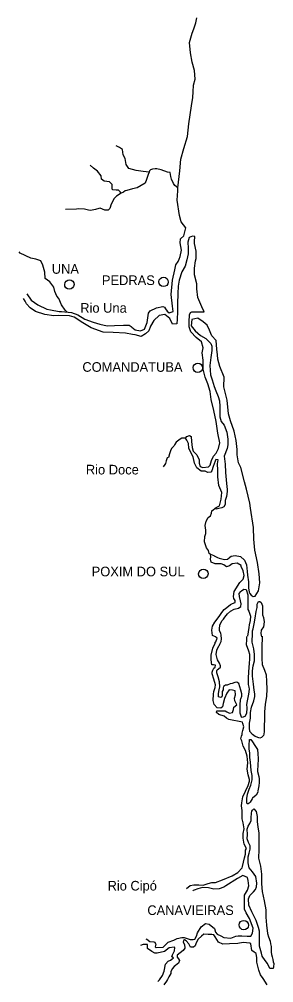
# Model space of a CAD drawing. Extents: x 662444 to 1640468, y 7452018 to 9606170.
# Drawn here: x 1133368 to 1150874, y 8253447 to 8319713 of the extents above; entities that cross this region are included whole.
import ezdxf

# ---------------------------------------------------------------- set-up
doc = ezdxf.new("R2010")
doc.units = 0
for name, color, linetype in [('Level 1', 7, 'Continuous'), ('Level 2', 7, 'Continuous'), ('Level 3', 7, 'Continuous')]:
    doc.layers.add(name, color=color, linetype=linetype)

msp = doc.modelspace()

# ---------------------------------------------------------------- linework, layer by layer
at = {"layer": 'Level 1'}
for points in [[(1145428, 8319196), (1145526, 8319459), (1145579, 8319802)], [(1133894, 8300837), (1134195, 8300395), (1134639, 8300072), (1135257, 8299766), (1135505, 8299737), (1136106, 8299609), (1136268, 8299616), (1136957, 8299553), (1137395, 8299396), (1137883, 8299082), (1138449, 8298878), (1138920, 8298732), (1139414, 8298618), (1139911, 8298649), (1140548, 8298664), (1140937, 8298665), (1141075, 8298583), (1141106, 8298527), (1141350, 8298364), (1141703, 8298277), (1141988, 8298402), (1142162, 8298865), (1142256, 8299507), (1142379, 8299671), (1142805, 8299859), (1143250, 8299958), (1143357, 8299922), (1143429, 8299797), (1143543, 8299627), (1143670, 8299524), (1143953, 8299616), (1143899, 8299984), (1143813, 8300776), (1143905, 8301764), (1144065, 8302471), (1144139, 8302825), (1144308, 8303054), (1144377, 8303208), (1144447, 8303406), (1144534, 8303837), (1144440, 8304329), (1144469, 8304606), (1144691, 8304823), (1144825, 8305364), (1144502, 8305773), (1144395, 8306221), (1144230, 8307271), (1144279, 8307904), (1144285, 8308115), (1144425, 8309279), (1144491, 8310089), (1144695, 8310829), (1144934, 8311656), (1145022, 8312521), (1145218, 8313761), (1145310, 8314337), (1145331, 8314726), (1145365, 8315181), (1145463, 8315601), (1145425, 8316180), (1145268, 8316763), (1145145, 8317400), (1145090, 8318125), (1145269, 8318765), (1145374, 8319051), (1145428, 8319196)], [(1142306, 8309193), (1141897, 8309237), (1141413, 8309306), (1140910, 8309453), (1140723, 8309725), (1140658, 8310139), (1140525, 8310387), (1140497, 8310566), (1140459, 8310745), (1140258, 8310895), (1140045, 8311012)], [(1144285, 8308115), (1144063, 8308277), (1143980, 8308413), (1143848, 8308705), (1143789, 8308907), (1143753, 8309175), (1143559, 8309192), (1143132, 8309359), (1142842, 8309434), (1142713, 8309437), (1142539, 8309409), (1142397, 8309368), (1142320, 8309292), (1142306, 8309193), (1142237, 8309039), (1142130, 8308686), (1142027, 8308444), (1141488, 8308114), (1141162, 8308045), (1140760, 8307945), (1140651, 8307903), (1140530, 8307829), (1140377, 8307755), (1140047, 8307542), (1139903, 8307390), (1139698, 8306995), (1139603, 8306687), (1139492, 8306578), (1139244, 8306585), (1138934, 8306716), (1138684, 8306645), (1138608, 8306625), (1138271, 8306567), (1138121, 8306583), (1137853, 8306657), (1137464, 8306667), (1137313, 8306660), (1136546, 8306637)], [(1140377, 8307755), (1140315, 8307846), (1140199, 8307949), (1140037, 8307965), (1139778, 8307972), (1139750, 8308106), (1139756, 8308339), (1139577, 8308522), (1139212, 8308588), (1139021, 8308715), (1138995, 8308950), (1138755, 8309268), (1138480, 8309475), (1138237, 8309671)], [(1145446, 8304769), (1145295, 8304806), (1145055, 8304702), (1144960, 8304393), (1144992, 8303980), (1144981, 8303580), (1144894, 8303160), (1144774, 8302730), (1144558, 8302346), (1144359, 8301773), (1144293, 8301364), (1144279, 8300852), (1144260, 8300152), (1144244, 8299586), (1144230, 8299085), (1144211, 8298775), (1143918, 8298738), (1143724, 8299133), (1143386, 8299398), (1142985, 8299342), (1142630, 8298985), (1142404, 8298613), (1142287, 8298283), (1142054, 8298089), (1141758, 8297897), (1141340, 8297998), (1141157, 8298036), (1140674, 8298116), (1139822, 8298173), (1139132, 8298203), (1138320, 8298492), (1137747, 8298842), (1137153, 8299214), (1136832, 8299323), (1136098, 8299343), (1135741, 8299308), (1135118, 8299414), (1134487, 8299609), (1134126, 8299864), (1133854, 8300149), (1133772, 8300329), (1133658, 8300499)], [(1147062, 8293779), (1147151, 8293476), (1147161, 8293076), (1147163, 8292364), (1147261, 8292039), (1147470, 8291788), (1147640, 8291305), (1147724, 8290824), (1147713, 8290435), (1147674, 8290181), (1147454, 8289675), (1147535, 8289106), (1147563, 8288549), (1147628, 8287779), (1147671, 8287378), (1147667, 8287244), (1147614, 8286890), (1147541, 8286614), (1147523, 8286347), (1147443, 8286183), (1147300, 8286109), (1147105, 8286059), (1146920, 8286020), (1146913, 8286131), (1147132, 8286247), (1147263, 8286700), (1147298, 8287166), (1147106, 8287638), (1147026, 8288241), (1147028, 8288708), (1146997, 8289143), (1147048, 8289408), (1146897, 8289424), (1146840, 8289314), (1146711, 8288951), (1146606, 8288653), (1146538, 8288566), (1146343, 8288538), (1146151, 8288622), (1145871, 8288629), (1145587, 8288871), (1145433, 8289175), (1145337, 8289612), (1145153, 8289962), (1145030, 8290210), (1145007, 8290544), (1144906, 8290770), (1144812, 8290906), (1144902, 8291014), (1145087, 8291076), (1145204, 8291006), (1145227, 8290683), (1145269, 8290259), (1145338, 8290001), (1145579, 8289750), (1145742, 8289412), (1145735, 8289178), (1145815, 8288953), (1145986, 8288893), (1146397, 8288926), (1146498, 8289035), (1146582, 8289355), (1146731, 8289662), (1146920, 8289879), (1147080, 8290186), (1147156, 8290584), (1147034, 8291244), (1146916, 8292048), (1146754, 8292798), (1146570, 8293570), (1146510, 8294106), (1146341, 8294645), (1146149, 8295095), (1146024, 8295654), (1146008, 8296256), (1145958, 8296780), (1146021, 8297112), (1145914, 8297537), (1145534, 8297815), (1145178, 8298214), (1145058, 8298562), (1145056, 8298896), (1145070, 8299396), (1145150, 8299549), (1145248, 8299602), (1145497, 8299595), (1145950, 8299583), (1146091, 8299601), (1145938, 8299928), (1145643, 8300581), (1145584, 8301183), (1145593, 8301528), (1145427, 8302144), (1145418, 8302601), (1145486, 8303099), (1145534, 8303265), (1145537, 8303765), (1145433, 8304302), (1145427, 8304491), (1145444, 8304702), (1145446, 8304769)], [(1136629, 8299583), (1136529, 8299712), (1136280, 8300072), (1136098, 8300510), (1135962, 8300659), (1135819, 8300985), (1135752, 8301298), (1135460, 8301651), (1135142, 8301893), (1135132, 8302316), (1134995, 8302809), (1134862, 8303091), (1134509, 8303223), (1134165, 8303276), (1133441, 8303630), (1133368, 8303710)], [(1146988, 8278454), (1147167, 8278694), (1147314, 8278912), (1147460, 8279119), (1147636, 8279259), (1147901, 8279452), (1148043, 8279537), (1148218, 8279599), (1148222, 8279743), (1148118, 8279879), (1148111, 8280013), (1148163, 8280345), (1148311, 8280608), (1148390, 8280728), (1148537, 8280969), (1148781, 8281195), (1148842, 8281450), (1148776, 8281785), (1148632, 8282067), (1148634, 8282134), (1148358, 8282297), (1148012, 8282263), (1147836, 8282123), (1147618, 8282062), (1147450, 8282201), (1147257, 8282262), (1146847, 8282251), (1146581, 8282381), (1146532, 8282582), (1146537, 8282738), (1146520, 8282916), (1146755, 8282832), (1146787, 8282798), (1146999, 8282692), (1147128, 8282655), (1147492, 8282567), (1147698, 8282583), (1147819, 8282669), (1147852, 8282712), (1147951, 8282776), (1148212, 8282835), (1148577, 8282770), (1148872, 8282517), (1149002, 8282179), (1149044, 8281733), (1149069, 8281477), (1149132, 8281019), (1149131, 8280618), (1149187, 8280316), (1149228, 8280226), (1149321, 8280101), (1149449, 8280020), (1149600, 8280027), (1149826, 8280410), (1149917, 8280941), (1149881, 8281565), (1149763, 8282358), (1149581, 8283197), (1149495, 8283945), (1149474, 8284758), (1149275, 8286098), (1149241, 8286422), (1149009, 8287385), (1148861, 8287900), (1148619, 8288875), (1148456, 8289213), (1148352, 8289761), (1148363, 8290128), (1148294, 8290742), (1148150, 8291391), (1147900, 8292087), (1147773, 8292569), (1147659, 8293507), (1147447, 8294425), (1147455, 8295092), (1147162, 8295834), (1147036, 8296327), (1147012, 8296639), (1146969, 8297030), (1146920, 8297609), (1146616, 8297940), (1146556, 8298098), (1146455, 8298334), (1146292, 8298683), (1146017, 8298902), (1145657, 8299157), (1145233, 8299058), (1145200, 8298625), (1145460, 8298273), (1145840, 8297962), (1146201, 8297763), (1146537, 8297420), (1146607, 8297229), (1146621, 8296928), (1146542, 8296441), (1146484, 8295897), (1146520, 8295263), (1146640, 8294903), (1146778, 8294454), (1146889, 8294162), (1147062, 8293779)], [(1144812, 8290906), (1144553, 8290902), (1144444, 8290838), (1144168, 8290634), (1144055, 8290448), (1144009, 8290350), (1143843, 8290199), (1143763, 8290034), (1143692, 8289814), (1143632, 8289582), (1143544, 8289540), (1143463, 8289353), (1143426, 8289165), (1143381, 8289088), (1143257, 8288925)], [(1146520, 8282916), (1146436, 8282974), (1146376, 8283165), (1146252, 8283369), (1146112, 8283762), (1146123, 8284129), (1146204, 8284338), (1146200, 8284572), (1146155, 8284884), (1146217, 8285183), (1146364, 8285435), (1146519, 8285564), (1146599, 8285739), (1146626, 8285905), (1146913, 8286131)], [(1149004, 8277252), (1148997, 8277029), (1148988, 8276707), (1149138, 8276280), (1149196, 8276045), (1149218, 8275699), (1149189, 8275422), (1149140, 8274823), (1149117, 8274390), (1149105, 8273967), (1149164, 8273765), (1149182, 8273643), (1149129, 8273299), (1149040, 8272846), (1149011, 8272580), (1149027, 8272357), (1148994, 8271957), (1148880, 8271760), (1148695, 8271699), (1148664, 8271722), (1148563, 8271981), (1148558, 8272170), (1148568, 8272537), (1148590, 8272925), (1148613, 8272980), (1148672, 8273156), (1148676, 8273312), (1148608, 8273559), (1148539, 8273794), (1148481, 8274018), (1148343, 8274111), (1148203, 8274104), (1148017, 8274032), (1147876, 8274002), (1147669, 8273919), (1147550, 8273922), (1147418, 8273815), (1147405, 8273726), (1147401, 8273593), (1147333, 8273472), (1147330, 8273384), (1147324, 8273161), (1147301, 8273117), (1147225, 8273075), (1147085, 8273101), (1147081, 8273346), (1147131, 8273589), (1147169, 8273789), (1147147, 8274134), (1147059, 8274481), (1146959, 8274762), (1146964, 8274907), (1146987, 8274973), (1147064, 8275026), (1147208, 8275144), (1147210, 8275244), (1147140, 8275436), (1147006, 8275651), (1146909, 8276020), (1146950, 8276331), (1147030, 8276484), (1147120, 8276637), (1147142, 8276659), (1147177, 8276725), (1147258, 8276923), (1147273, 8277100), (1147259, 8277345), (1147231, 8277491), (1147149, 8277660), (1147142, 8277794), (1147160, 8278038), (1147298, 8278334), (1147409, 8278453), (1147520, 8278584), (1147689, 8278824), (1147909, 8278995), (1148161, 8279133), (1148455, 8279203), (1148620, 8279320), (1148625, 8279509), (1148577, 8279711), (1148510, 8280013), (1148505, 8280213), (1148617, 8280355), (1148661, 8280398), (1148826, 8280505), (1148987, 8280500), (1149085, 8280130), (1149095, 8279729), (1149086, 8279418), (1149088, 8279107), (1149172, 8279004), (1149270, 8278668), (1149262, 8278368), (1149188, 8278058), (1149161, 8277870), (1149110, 8277593), (1149069, 8277283)], [(1150072, 8277277), (1150067, 8277088), (1150066, 8276688), (1150053, 8276232), (1150050, 8275754), (1150071, 8275341), (1150233, 8274948), (1150353, 8274633), (1150383, 8274165), (1150389, 8273631), (1150386, 8273152), (1150295, 8272577), (1150248, 8272077), (1150236, 8271666), (1150230, 8271455), (1150223, 8271199), (1150210, 8270732), (1150204, 8270543), (1150169, 8270444), (1150025, 8270304), (1149916, 8270262), (1149596, 8270383), (1149406, 8270511), (1149239, 8270716), (1149203, 8270972), (1149212, 8271295), (1149265, 8271638), (1149276, 8272027), (1149351, 8272403), (1149504, 8272833), (1149566, 8273131), (1149571, 8273309), (1149525, 8273577), (1149472, 8273990), (1149412, 8274526), (1149422, 8274893), (1149464, 8275236), (1149549, 8275579), (1149562, 8276034), (1149497, 8276403), (1149392, 8276874), (1149396, 8277018), (1149406, 8277363), (1149414, 8277640), (1149461, 8277784), (1149536, 8278138), (1149600, 8278514), (1149667, 8278979), (1149729, 8279256), (1149736, 8279489), (1149827, 8279675), (1149913, 8279673), (1150008, 8279604), (1150110, 8279367), (1150106, 8279245), (1150091, 8279078), (1150092, 8278745), (1150163, 8278576), (1150219, 8278263), (1150166, 8277931), (1150019, 8277690), (1149980, 8277458), (1150038, 8277233)], [(1144879, 8259939), (1145133, 8260132), (1145382, 8260180), (1145716, 8260171), (1146017, 8260162), (1146355, 8260275), (1146615, 8260345), (1146863, 8260338), (1147354, 8260536), (1148019, 8260795), (1148413, 8261028), (1148703, 8261354), (1148716, 8261431), (1148873, 8262027), (1148923, 8262282), (1148931, 8262571), (1148989, 8262680), (1148835, 8262974), (1148772, 8263387), (1148781, 8263721), (1148833, 8264031), (1148769, 8264444), (1148713, 8264724), (1148697, 8265303), (1148663, 8265615), (1148668, 8265815), (1148755, 8266224), (1148939, 8266620), (1149122, 8267004), (1149196, 8267302), (1149210, 8267435), (1149111, 8267749), (1149057, 8268129), (1149091, 8268562), (1149051, 8269041), (1148921, 8269412), (1148779, 8269716), (1148671, 8270075), (1148621, 8270233), (1148648, 8270410), (1148694, 8270531), (1148697, 8270620), (1148745, 8270807), (1148806, 8271039), (1148748, 8271275), (1148718, 8271375), (1147785, 8271558), (1147626, 8271640), (1147458, 8271789), (1147105, 8271888), (1146936, 8272038), (1146950, 8272137), (1147166, 8272154), (1147306, 8272150), (1147543, 8272143), (1147649, 8272073), (1147830, 8271979), (1148036, 8272029), (1148117, 8272238), (1148122, 8272393), (1148342, 8272565), (1148188, 8272825), (1148172, 8273015), (1148254, 8273246), (1148218, 8273514), (1148037, 8273575), (1147800, 8273582), (1147642, 8273352), (1147492, 8272990), (1147396, 8272648), (1147346, 8272427), (1147236, 8272341), (1146977, 8272348), (1146779, 8272587), (1146712, 8272867), (1146724, 8273289), (1146751, 8273478), (1146845, 8273764), (1146860, 8273931), (1146764, 8274323), (1146644, 8274682), (1146648, 8274804), (1146673, 8274948), (1146753, 8275079), (1146852, 8275155), (1146867, 8275299), (1146727, 8275303), (1146608, 8275317), (1146564, 8275652), (1146573, 8275974), (1146684, 8276461), (1146834, 8276801), (1146847, 8276879), (1146901, 8276888), (1146973, 8277153), (1146857, 8277245), (1146665, 8277340), (1146622, 8277697), (1146651, 8277974), (1146831, 8278236), (1146988, 8278454)], [(1149812, 8266595), (1149654, 8266343), (1149422, 8266150), (1149388, 8266095), (1149263, 8265876), (1149185, 8265789), (1149119, 8265758), (1149044, 8265760), (1149014, 8265850), (1149022, 8266128), (1149074, 8266427), (1149180, 8266768), (1149296, 8267032), (1149382, 8267408), (1149390, 8267697), (1149325, 8268043), (1149276, 8268612), (1149221, 8268936), (1149229, 8269248), (1149183, 8269527), (1149193, 8269860), (1149199, 8270083), (1149202, 8270172), (1149288, 8270169), (1149413, 8270021), (1149579, 8269772), (1149754, 8269488), (1149788, 8269187), (1149812, 8268875), (1149808, 8268753), (1149769, 8268487), (1149754, 8267965), (1149852, 8267639), (1149879, 8267460), (1149862, 8267227), (1149855, 8266994), (1149791, 8266640)], [(1150703, 8255546), (1150731, 8255400), (1150758, 8255232), (1150818, 8255053), (1150824, 8254886), (1150874, 8254762), (1150868, 8254540), (1150832, 8254418), (1150617, 8254436), (1150454, 8254774), (1150277, 8254979), (1150081, 8255285), (1150022, 8255487), (1149885, 8255958), (1149894, 8256292), (1149884, 8256681), (1149893, 8256993), (1149835, 8257239), (1149666, 8257733), (1149360, 8258332), (1149157, 8258771), (1149148, 8259216), (1149230, 8259448), (1149475, 8259708), (1149609, 8259860), (1149689, 8260035), (1149707, 8260291), (1149645, 8260760), (1149417, 8261066), (1149177, 8261351), (1149122, 8261698), (1149123, 8262098), (1149173, 8262364), (1149246, 8262629), (1149252, 8262862), (1149141, 8263099), (1149050, 8263335), (1149059, 8263646), (1149048, 8264014), (1149108, 8264212), (1149232, 8264398), (1149323, 8264595), (1149329, 8264795), (1149349, 8265106), (1149364, 8265250), (1149420, 8265327), (1149497, 8265402), (1149675, 8265219), (1149741, 8264884), (1149731, 8264517), (1149775, 8264171), (1149838, 8263724), (1149852, 8263090), (1149838, 8262601), (1149832, 8262022), (1149956, 8261463), (1150026, 8260904), (1150030, 8260259), (1150079, 8259713), (1150222, 8259074), (1150323, 8258460), (1150330, 8257948), (1150368, 8257413), (1150449, 8256843), (1150507, 8256608), (1150639, 8256315), (1150644, 8256126), (1150692, 8255935), (1150703, 8255546)], [(1142076, 8256459), (1142140, 8256435), (1142351, 8256273), (1142630, 8256254), (1142673, 8256253), (1142766, 8256095), (1142728, 8255907), (1142792, 8255860), (1143256, 8255903), (1143621, 8256237), (1144002, 8256382), (1144221, 8256498), (1144546, 8256556), (1144708, 8256551), (1145124, 8256417), (1145339, 8256411), (1145438, 8256453), (1145551, 8256650), (1145622, 8256881), (1145882, 8257285), (1146179, 8257521), (1146426, 8257470), (1146794, 8257170), (1146873, 8256923), (1146978, 8256798), (1147233, 8256679), (1147445, 8256562), (1147918, 8256504), (1148256, 8256650), (1148429, 8256679), (1148687, 8256671), (1149043, 8256661), (1149290, 8256643), (1149404, 8256851), (1149468, 8257194), (1149206, 8257858), (1148970, 8258265), (1148869, 8258501), (1148853, 8259069), (1148864, 8259469), (1149058, 8259820), (1149163, 8260106), (1149109, 8260475), (1149072, 8260687), (1148741, 8260819), (1148380, 8260607), (1147590, 8260117), (1147446, 8260010), (1147120, 8259897), (1146742, 8259875), (1146379, 8259985), (1145970, 8259997), (1145654, 8259906), (1145404, 8259824), (1145328, 8259781), (1145305, 8259749)], [(1150423, 8253307), (1150144, 8253737), (1149968, 8253987), (1149859, 8254302), (1149713, 8254873), (1149722, 8255162), (1149665, 8255453), (1149528, 8255546), (1149359, 8255673), (1149308, 8256131), (1149234, 8256177), (1148782, 8256224), (1148393, 8256157), (1147831, 8256117), (1147367, 8256108), (1147080, 8256228), (1146854, 8256612), (1146750, 8256738), (1146610, 8256764), (1146373, 8256771), (1146061, 8256780), (1145906, 8256639), (1145664, 8256446), (1145538, 8256194), (1145468, 8255996), (1145357, 8255888), (1145152, 8255893), (1145040, 8256119), (1144841, 8256325), (1144746, 8256394), (1144670, 8256363), (1144634, 8256242), (1144727, 8256084), (1144762, 8255827), (1144650, 8255674), (1144441, 8255502), (1144221, 8255353), (1144238, 8255208), (1144321, 8255094), (1144383, 8254981), (1144313, 8254794), (1144026, 8254569), (1143881, 8254395), (1143801, 8254208), (1143786, 8254086), (1143650, 8253845), (1143570, 8253681), (1143491, 8253560), (1143322, 8253309)], [(1142898, 8253533), (1143009, 8253652), (1143222, 8253946), (1143338, 8254232), (1143438, 8254719), (1143605, 8254925), (1143780, 8254998), (1143868, 8255062), (1143979, 8255170), (1143873, 8255229), (1143909, 8255362), (1144057, 8255635), (1144064, 8255880), (1144021, 8255903), (1143675, 8255846), (1143355, 8255589), (1142856, 8255480), (1142684, 8255485), (1142493, 8255591), (1142198, 8255811), (1142201, 8255944), (1142194, 8256066), (1142097, 8256080), (1141893, 8256086), (1141697, 8256014)]]:
    msp.add_lwpolyline(points, dxfattribs=at)
at = {"layer": 'Level 2'}
for centre in [(1143297, 8301647), (1136815, 8301469), (1145649, 8295743), (1146029, 8281573), (1148816, 8257413)]:
    msp.add_ellipse(centre, major_axis=(323, -9), ratio=0.999997, dxfattribs=at)

# ---------------------------------------------------------------- texts
at = {"layer": 'Level 3'}
for s, height, p in [('UNA', 662.3, (1135604, 8302209)), ('PEDRAS', 662.4, (1139052, 8301434)), ('Rio Una', 662.3, (1137563, 8299531)), ('COMANDATUBA', 662.2, (1137711, 8295467)), ('Rio Doce', 662, (1137950, 8288407)), ('POXIM DO SUL', 661.81, (1138350, 8281400)), ('Rio Cipó', 661.2, (1139444, 8259790)), ('CANAVIEIRAS', 661.18, (1142179, 8258106))]:
    msp.add_text(s, height=height, dxfattribs=at).set_placement(p)

doc.saveas('drawing.dxf')
